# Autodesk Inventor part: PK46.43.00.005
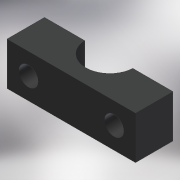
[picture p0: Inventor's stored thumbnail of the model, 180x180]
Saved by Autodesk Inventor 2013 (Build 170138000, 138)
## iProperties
Created: 2005-05
Part Number: PK46.43.00.005
Document SubType Name: Modeling
Designer: elarisa
Manufacturer: Standard
Standards Organization: Custom
Material: Silicone
Density: 1.25 g/cm^3
Author: elarisa
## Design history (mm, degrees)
sketch "Эскиз1"
  geometry: L1 (-57.8, -15.2)-(-57.8, 19.8); L2 (62.2, 19.8)-(62.2, -15.2); L3 (62.2, -15.2)-(-57.8, -15.2); L4 (-57.8, 19.8)-(-20.278, 19.8); L5 (24.678, 19.8)-(62.2, 19.8); A1 r 22.5 centre (2.2, 20.8) between (-20.278, 19.8) and (24.678, 19.8)
  constraints: 10 end point, 3 parallel, 2 perpendicular, 2 point on circle, 1 centre point, 1 vertical, 1 other
  dimensions: "d0" = 35 distance between parallel lines of L3 L4; "d1" = 1 distance from line of L4 A1.centre; "d2" = 0 distance between parallel lines of L4 L5; "d3" = 60 distance from line of A1.centre L1 (= 0.5 x d4); "d4" = 120 distance of L2.end L1.start; "d5" = 22.5 radius of A1
extrude "Выдавливание1" new body sketch "Эскиз1" distance "d6" = 40; taper "d7" = 0 deg
sketch "Эскиз2"
  geometry: L1 (0, 0)-(0, 40) reference; L2 (120, 0)-(0, 0) reference; 2 further points
  dimensions: "d8" = 20 distance from line of L2 point (20, 20); "d9" = 20 distance from line of L1 point (20, 20); "d10" = 80 distance of point (100, 20) point (20, 20); "d11" = 0 vertical distance of point (100, 20) point (20, 20)
hole "Отверстие1" sketch "Эскиз2" diameter "d12" = 18; stored, may be unused: countersink angle "d16" = 90 deg, drill point angle "d18" = 118 deg; dims "d13" = 6, "d14" = 4, "d15" = 2, "d17" = 8
body "Solid1"
